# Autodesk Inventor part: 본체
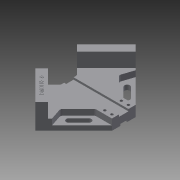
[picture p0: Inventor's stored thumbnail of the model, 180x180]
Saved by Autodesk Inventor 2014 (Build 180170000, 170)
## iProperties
Created: 2019-04
Part Number: 본체
Material: Generic
Document SubType Name: Modeling
Designer: kh
Density: 1 g/cm^3
Appearance: Default
Author: kh
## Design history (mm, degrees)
sketch "Sketch1"
  geometry: L1 (-20, 20)-(20, 20); L2 (20, 20)-(84.853, 84.853); L3 (84.853, 84.853)-(35.355, 134.35); L4 (35.355, 134.35)-(14.005, 113); L5 (14.005, 113)-(-14.005, 113); L6 (0, 20)-(0, 113); L7 (-20, 20)-(-84.853, 84.853); L8 (-84.853, 84.853)-(-35.355, 134.35); L9 (-35.355, 134.35)-(-14.005, 113); L10 (35.355, 134.35)-(-29.885, 199.591); L11 (-35.355, 134.35)-(31.912, 201.618); 1 further point
  constraints: 22 end point, 5 perpendicular, 3 symmetric about line, 2 midpoint, 2 parallel, 1 horizontal, 1 vertical alignment
  dimensions: "d3" = 40 distance of L1.end L1.start; "d39" = 120 distance of point (0, 0) L7.end; "d41" = 20 distance from line of point (0, 0) L1; "d42" = 93 distance between parallel lines of L1 L5; "d43" = 70 distance of L2.end L3.end
extrude "Extrusion1" new body sketch "Sketch1" distance "d11" = 42; taper "d12" = 0 deg
sketch "Sketch2"
  geometry: L1 (20, 20)-(-20, 20) reference; L2 (-20, 20)-(-84.853, 84.853) reference; L3 (-84.853, 84.853)-(-35.355, 134.35) reference; L4 (-35.355, 134.35)-(-14.005, 113) reference; L5 (-14.005, 113)-(14.005, 113) reference; L6 (14.005, 113)-(35.355, 134.35) reference; L7 (35.355, 134.35)-(84.853, 84.853) reference; L8 (84.853, 84.853)-(20, 20) reference; L9 (24.749, 123.744)-(74.246, 74.246); L10 (-74.178, 74.178)-(-24.68, 123.675); L11 (-24.68, 123.675)-(-14.005, 113); L12 (14.005, 113)-(-14.005, 113); L13 (74.246, 74.246)-(20, 20); L14 (20, 20)-(-20, 20); L15 (-20, 20)-(-74.178, 74.178); L16 (14.005, 113)-(24.749, 123.744)
  constraints: 16 end point, 4 perpendicular, 3 collinear, 3 point on line, 1 midpoint
  dimensions: "d46" = 15 distance between parallel lines of L7 L9
extrude "Extrusion2" cut sketch "Sketch2" distance "d15" = 24; taper "d16" = 0 deg
sketch "Sketch3"
  geometry: L1 (-8, 113)-(8, 113); L2 (8, 113)-(8, 20); L3 (8, 20)-(-8, 20); L4 (-8, 20)-(-8, 113); L5 (20, 20)-(-20, 20) reference; 2 further points
  constraints: 8 end point, 2 parallel, 1 horizontal, 1 midpoint, 1 perpendicular, 1 point on line, 1 vertical alignment
  dimensions: "d17" = 16 distance of L2.end L3.end; "d18" = 93 distance of L1.end L2.end
extrude "Extrusion3" cut sketch "Sketch3" distance "d19" = 3.5; taper "d20" = 0 deg
sketch "Sketch4"
  geometry: L1 (-6, 113)-(6, 113); L2 (6, 113)-(6, 20); L3 (6, 20)-(-6, 20); L4 (-6, 20)-(-6, 113); L5 (20, 20)-(-20, 20) reference; 2 further points
  constraints: 8 end point, 2 parallel, 1 horizontal, 1 midpoint, 1 perpendicular, 1 point on line, 1 vertical alignment
  dimensions: "d21" = 12 distance of L1.start L1.end; "d22" = 93 distance of L1.end L2.end
extrude "Extrusion4" cut sketch "Sketch4" distance "d23" = 3; taper "d24" = 0 deg
sketch "Sketch5"
  geometry: L1 (-70.711, 70.711)-(-49.497, 77.782); L2 (-49.497, 77.782)-(-20, 48.284); L3 (-20, 48.284)-(-20, 20); L4 (-20, 20)-(-70.711, 70.711); L5 (-84.853, 84.853)-(-20, 20) reference; L6 (-35.355, 134.35)-(-84.853, 84.853) reference; L7 (8, 20)-(-8, 20) reference; 1 further point
  constraints: 8 end point, 1 collinear, 1 parallel, 1 vertical
  dimensions: "d25" = 20 distance of L1.start L5.start; "d27" = 30 distance from line of L6 L1.end; "d28" = 20 horizontal distance of L3.end point (0, 0); "d29" = 20 distance between parallel lines of L2 L4
extrude "Extrusion5" cut sketch "Sketch5" distance "d30" = 10; taper "d31" = 0 deg
sketch "Sketch6"
  geometry: L1 (-49.497, 63.64)-(-32.527, 46.669); L2 (-52.679, 60.458)-(-35.709, 43.487); L3 (-29.345, 49.851)-(-46.315, 66.822); L4 (-84.853, 84.853)-(-20, 20) reference; L5 (-35.355, 134.35)-(-84.853, 84.853) reference; A1 r 4.5 centre (-49.497, 63.64) between (-46.315, 66.822) and (-52.679, 60.458); A2 r 4.5 centre (-32.527, 46.669) between (-35.709, 43.487) and (-29.345, 49.851); 2 further points
  constraints: 8 end point, 4 point on circle, 4 tangent, 2 centre point, 2 parallel, 1 midpoint
  dimensions: "d32" = 10 distance from line of L1.start L4; "d33" = 40 distance from line of L1.start L5; "d34" = 24 distance of L1.end L1.start; "d35" = 9 distance between parallel lines of L3 L2
extrude "Extrusion6" cut sketch "Sketch6" stored distance "d36" = 10; taper "d37" = 0 deg
mirror "Mirror1"
sketch "Sketch7"
  geometry: L1 (-37.704, 116.532)-(-67.034, 87.201); L2 (-67.034, 87.201)-(-71.898, 92.065); L3 (-71.898, 92.065)-(-42.567, 121.395); L4 (-42.567, 121.395)-(-37.704, 116.532); L5 (-42.567, 121.395)-(-67.034, 87.201); L6 (-35.355, 134.35)-(-84.853, 84.853) reference; L7 (-24.68, 123.675)-(-35.355, 134.35) reference; 2 further points
  constraints: 2 end point, 1 midpoint, 2 other
  dimensions: "d47" = 7.5 distance from line of L6 point (-54.801, 104.298); "d48" = 35 distance from line of L7 point (-54.801, 104.298)
emboss "Emboss1" sketch "Sketch7" dims "d17" = 16, "d18" = 93, "d49" = 0.5, "d50" = 0
sketch "Sketch8"
  geometry: L1 (20, 20)-(6, 20) reference; 2 further points
  dimensions: "d51" = 6 distance from line of point (14, 26) L1; "d52" = 14 horizontal distance of point (14, 26) point (0, 0)
hole "Hole1" sketch "Sketch8" at (14, 26) diameter "d53" = 4.5; stored, may be unused: countersink angle "d57" = 90 deg, drill point angle "d59" = 0 deg; dims "d54" = 6, "d55" = 8, "d56" = 10, "d58" = 8
pattern_linear "Rectangular Pattern1" dims "d62" = 28, "d65" = 12
fillet "Fillet1" dims "d66" = 5
fillet "Fillet2" dims "d67" = 5
body "Solid1"
node "Project Cut Edges1"
